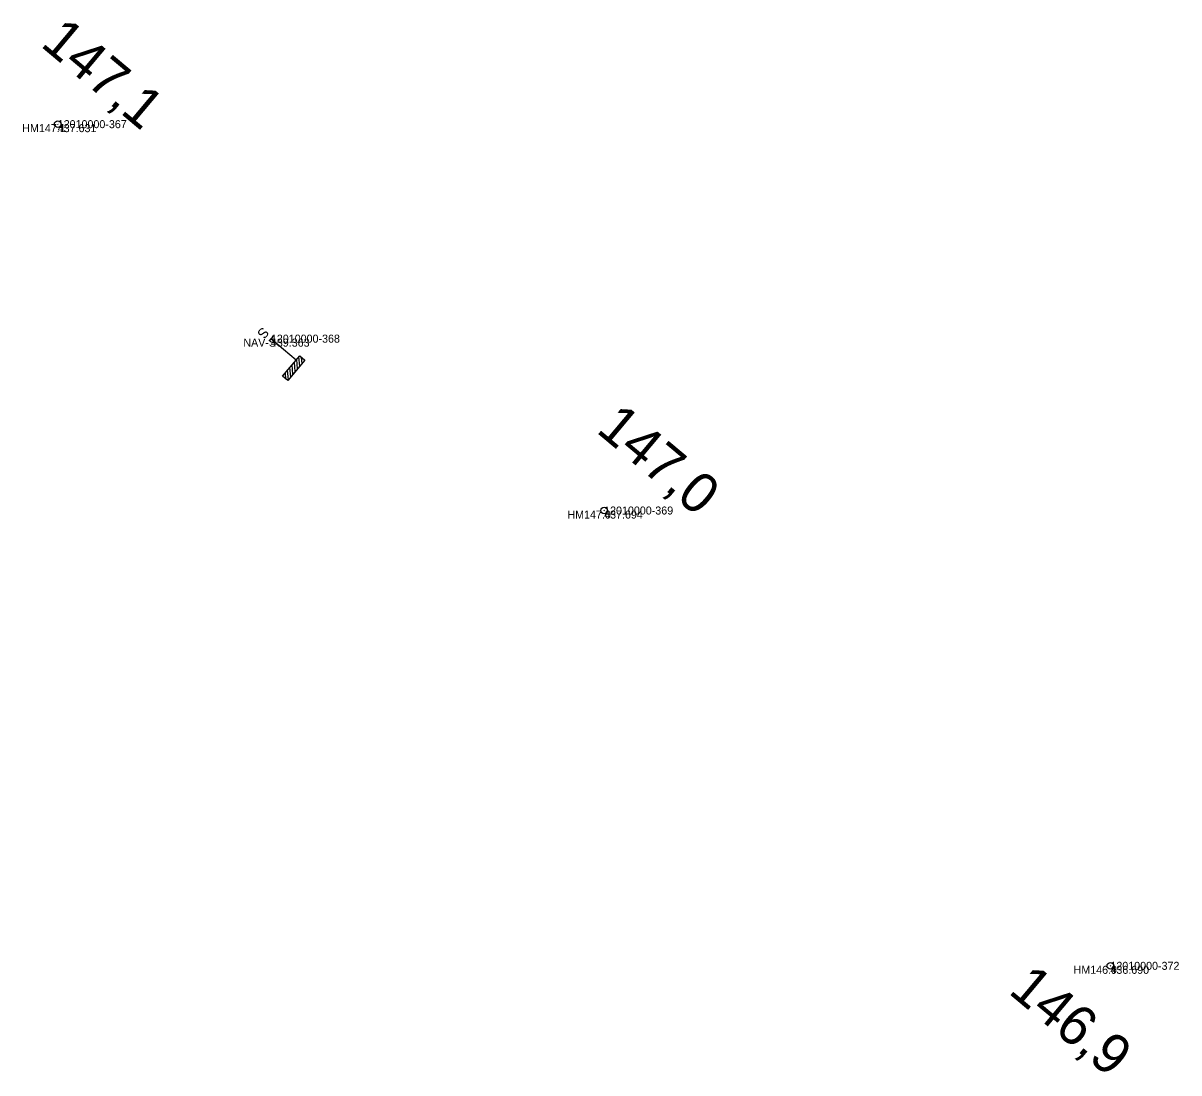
# Model space of a CAD drawing. Extents: x -653665 to -652742, y -1166300 to -1165487.
# Drawn here: x -653665 to -653491.7, y -1165644.1 to -1165486.6 of the extents above; entities that cross this region are included whole.
import ezdxf

# ---------------------------------------------------------------- set-up
doc = ezdxf.new("R2010")
doc.units = 0
for name, color, linetype in [('Vrstva 6', 7, 'Continuous'), ('Vrstva 60', 7, 'Continuous'), ('Vrstva 61', 7, 'Continuous'), ('Vrstva 62', 7, 'Continuous'), ('Vrstva 7', 7, 'Continuous')]:
    doc.layers.add(name, color=color, linetype=linetype)

msp = doc.modelspace()

# ---------------------------------------------------------------- linework, layer by layer
at = {"layer": 'Vrstva 6'}
for p, q in [((-653627.54, -1165533.55), (-653628.18, -1165534.32)), ((-653627.86, -1165533.94), (-653624.05, -1165537.14)), ((-653624.21, -1165538.88), (-653624.33, -1165537.47)), ((-653623.87, -1165538.48), (-653623.99, -1165537.07)), ((-653623.52, -1165538.07), (-653623.65, -1165536.66)), ((-653623.18, -1165537.66), (-653623.26, -1165536.75)), ((-653625.61, -1165540), (-653625.69, -1165539.1)), ((-653625.23, -1165540.1), (-653625.35, -1165538.69)), ((-653624.89, -1165539.69), (-653625.01, -1165538.28)), ((-653624.55, -1165539.29), (-653624.67, -1165537.88))]:
    msp.add_line(p, q, dxfattribs=at)
msp.add_lwpolyline([(-653623.53, -1165536.52), (-653622.77, -1165537.17), (-653625.34, -1165540.23), (-653626.11, -1165539.59)], close=True, dxfattribs=at)
at = {"layer": 'Vrstva 60'}
for p, q in [((-653659.83, -1165501.77), (-653659.83, -1165501.77)), ((-653627.86, -1165533.94), (-653627.86, -1165533.94)), ((-653577.88, -1165559.73), (-653577.88, -1165559.73)), ((-653501.95, -1165628.01), (-653501.95, -1165628.01))]:
    msp.add_line(p, q, dxfattribs=at)
at = {"layer": 'Vrstva 7'}
for p, q in [((-653659.87, -1165501.74), (-653659.79, -1165501.8)), ((-653577.92, -1165559.69), (-653577.84, -1165559.76)), ((-653501.99, -1165627.98), (-653501.91, -1165628.04))]:
    msp.add_line(p, q, dxfattribs=at)
for centre in [(-653659.83, -1165501.77), (-653577.88, -1165559.73), (-653501.95, -1165628.01)]:
    msp.add_circle(centre, 0.5, dxfattribs=at)

# ---------------------------------------------------------------- texts
at = {"layer": 'Vrstva 6'}
msp.add_text('S', height=1.5, rotation=230, dxfattribs=at).set_placement((-653629.15, -1165532.11))
at = {"layer": 'Vrstva 60'}
for s, p in [('12010000-367', (-653659.83, -1165502.37)), ('12010000-368', (-653627.86, -1165534.54)), ('12010000-369', (-653577.88, -1165560.32)), ('12010000-372', (-653501.95, -1165628.61))]:
    msp.add_text(s, height=1.2, dxfattribs=at).set_placement(p)
at = {"layer": 'Vrstva 61'}
for s, p in [('437.631', (-653659.83, -1165502.97)), ('439.363', (-653627.86, -1165535.14)), ('437.694', (-653577.88, -1165560.93)), ('436.690', (-653501.95, -1165629.21))]:
    msp.add_text(s, height=1.2, dxfattribs=at).set_placement(p)
at = {"layer": 'Vrstva 62'}
for s, p in [('HM147.1', (-653665.15, -1165502.97)), ('NAV-S', (-653631.99, -1165535.14)), ('HM147.0', (-653583.39, -1165560.93)), ('HM146.9', (-653507.47, -1165629.21))]:
    msp.add_text(s, height=1.2, dxfattribs=at).set_placement(p)
at = {"layer": 'Vrstva 7'}
for s, p in [('147,1', (-653662.57, -1165489.97)), ('147,0', (-653579.23, -1165547.86)), ('146,9', (-653517.41, -1165632.01))]:
    msp.add_text(s, height=6, rotation=320, dxfattribs=at).set_placement(p)

doc.saveas('drawing.dxf')
